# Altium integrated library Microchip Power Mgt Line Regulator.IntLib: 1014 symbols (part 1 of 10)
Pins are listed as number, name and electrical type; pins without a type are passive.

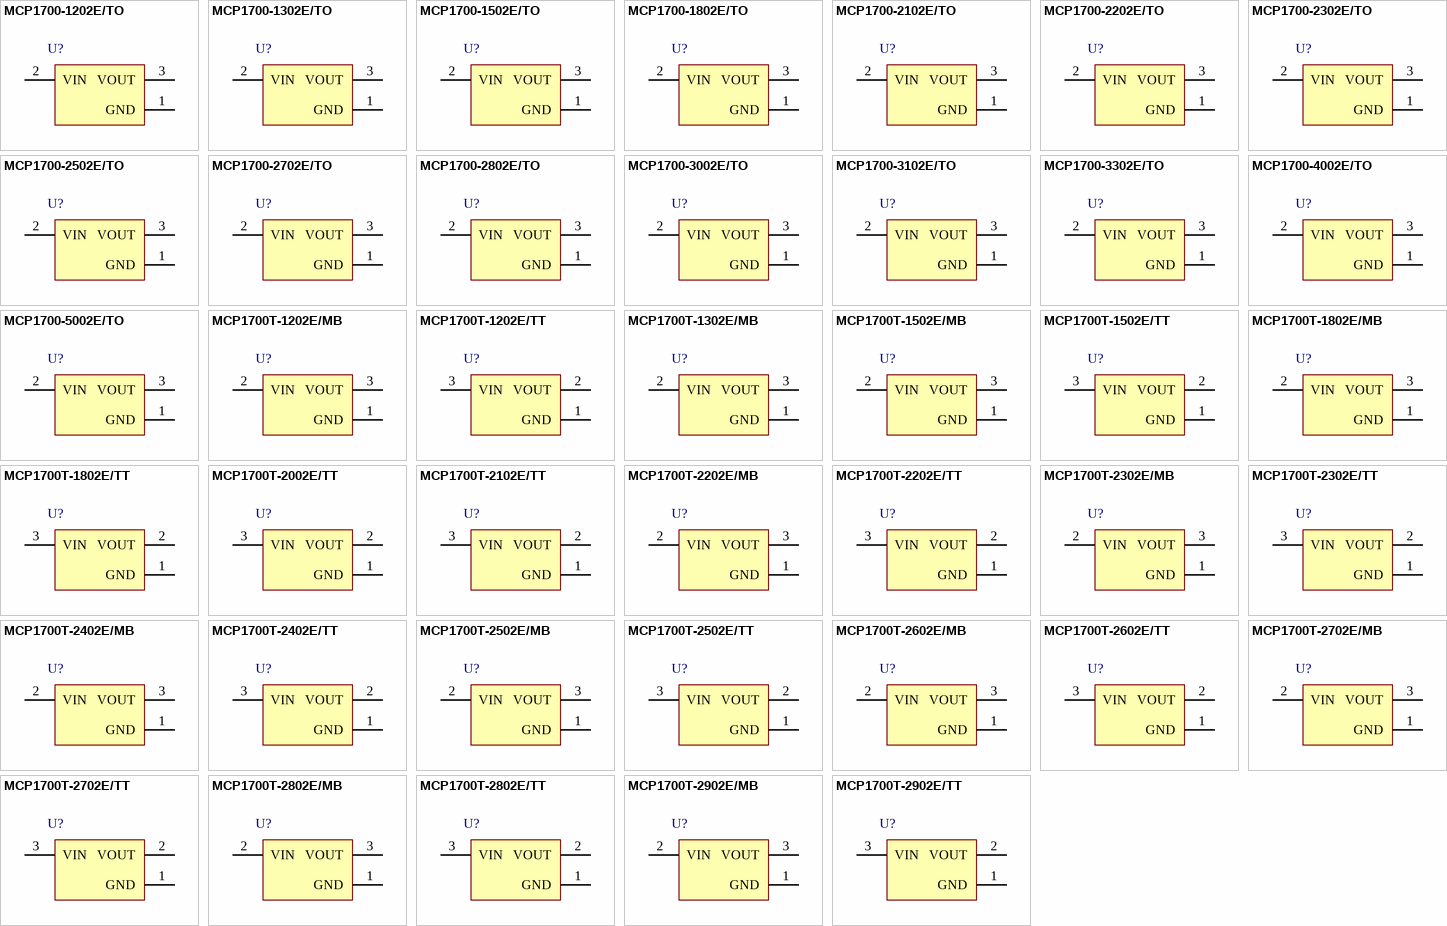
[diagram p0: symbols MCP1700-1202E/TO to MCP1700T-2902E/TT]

## MCP1700-1202E/TO
designator U?
Low Quiescent Current LDO, 3-Pin TO-92, Extended TemperatureBAG
footprint TO-92-TO3 (TO, Flat Index; 3 In-Line, Axial Leads; Body Dia. 4.8mm; Leads 0.56 x 0.53 mm (max))
pins: 1 GND (power), 2 VIN (power), 3 VOUT (power)

## MCP1700-1302E/TO
designator U?
Low Quiescent Current LDO, 3-Pin TO-92, Extended TemperatureBAG
footprint TO-92-TO3 (TO, Flat Index; 3 In-Line, Axial Leads; Body Dia. 4.8mm; Leads 0.56 x 0.53 mm (max))
pins: 1 GND (power), 2 VIN (power), 3 VOUT (power)

## MCP1700-1502E/TO
designator U?
Low Quiescent Current LDO, 3-Pin TO-92, Extended TemperatureBAG
footprint TO-92-TO3 (TO, Flat Index; 3 In-Line, Axial Leads; Body Dia. 4.8mm; Leads 0.56 x 0.53 mm (max))
pins: 1 GND (power), 2 VIN (power), 3 VOUT (power)

## MCP1700-1802E/TO
designator U?
Low Quiescent Current LDO, 3-Pin TO-92, Extended TemperatureBAG
footprint TO-92-TO3 (TO, Flat Index; 3 In-Line, Axial Leads; Body Dia. 4.8mm; Leads 0.56 x 0.53 mm (max))
pins: 1 GND (power), 2 VIN (power), 3 VOUT (power)

## MCP1700-2102E/TO
designator U?
Low Quiescent Current LDO, 3-Pin TO-92, Extended TemperatureBAG
footprint TO-92-TO3 (TO, Flat Index; 3 In-Line, Axial Leads; Body Dia. 4.8mm; Leads 0.56 x 0.53 mm (max))
pins: 1 GND (power), 2 VIN (power), 3 VOUT (power)

## MCP1700-2202E/TO
designator U?
Low Quiescent Current LDO, 3-Pin TO-92, Extended TemperatureBAG
footprint TO-92-TO3 (TO, Flat Index; 3 In-Line, Axial Leads; Body Dia. 4.8mm; Leads 0.56 x 0.53 mm (max))
pins: 1 GND (power), 2 VIN (power), 3 VOUT (power)

## MCP1700-2302E/TO
designator U?
Low Quiescent Current LDO, 3-Pin TO-92, Extended TemperatureBAG
footprint TO-92-TO3 (TO, Flat Index; 3 In-Line, Axial Leads; Body Dia. 4.8mm; Leads 0.56 x 0.53 mm (max))
pins: 1 GND (power), 2 VIN (power), 3 VOUT (power)

## MCP1700-2502E/TO
designator U?
Low Quiescent Current LDO, 3-Pin TO-92, Extended TemperatureBAG
footprint TO-92-TO3 (TO, Flat Index; 3 In-Line, Axial Leads; Body Dia. 4.8mm; Leads 0.56 x 0.53 mm (max))
pins: 1 GND (power), 2 VIN (power), 3 VOUT (power)

## MCP1700-2702E/TO
designator U?
Low Quiescent Current LDO, 3-Pin TO-92, Extended TemperatureBAG
footprint TO-92-TO3 (TO, Flat Index; 3 In-Line, Axial Leads; Body Dia. 4.8mm; Leads 0.56 x 0.53 mm (max))
pins: 1 GND (power), 2 VIN (power), 3 VOUT (power)

## MCP1700-2802E/TO
designator U?
Low Quiescent Current LDO, 3-Pin TO-92, Extended TemperatureBAG
footprint TO-92-TO3 (TO, Flat Index; 3 In-Line, Axial Leads; Body Dia. 4.8mm; Leads 0.56 x 0.53 mm (max))
pins: 1 GND (power), 2 VIN (power), 3 VOUT (power)

## MCP1700-3002E/TO
designator U?
Low Quiescent Current LDO, 3-Pin TO-92, Extended TemperatureBAG
footprint TO-92-TO3 (TO, Flat Index; 3 In-Line, Axial Leads; Body Dia. 4.8mm; Leads 0.56 x 0.53 mm (max))
pins: 1 GND (power), 2 VIN (power), 3 VOUT (power)

## MCP1700-3102E/TO
designator U?
Low Quiescent Current LDO, 3-Pin TO-92, Extended TemperatureBAG
footprint TO-92-TO3 (TO, Flat Index; 3 In-Line, Axial Leads; Body Dia. 4.8mm; Leads 0.56 x 0.53 mm (max))
pins: 1 GND (power), 2 VIN (power), 3 VOUT (power)

## MCP1700-3302E/TO
designator U?
Low Quiescent Current LDO, 3-Pin TO-92, Extended TemperatureBAG
footprint TO-92-TO3 (TO, Flat Index; 3 In-Line, Axial Leads; Body Dia. 4.8mm; Leads 0.56 x 0.53 mm (max))
pins: 1 GND (power), 2 VIN (power), 3 VOUT (power)

## MCP1700-4002E/TO
designator U?
Low Quiescent Current LDO, 3-Pin TO-92, Extended TemperatureBAG
footprint TO-92-TO3 (TO, Flat Index; 3 In-Line, Axial Leads; Body Dia. 4.8mm; Leads 0.56 x 0.53 mm (max))
pins: 1 GND (power), 2 VIN (power), 3 VOUT (power)

## MCP1700-5002E/TO
designator U?
Low Quiescent Current LDO, 3-Pin TO-92, Extended TemperatureBAG
footprint TO-92-TO3 (TO, Flat Index; 3 In-Line, Axial Leads; Body Dia. 4.8mm; Leads 0.56 x 0.53 mm (max))
pins: 1 GND (power), 2 VIN (power), 3 VOUT (power)

## MCP1700T-1202E/MB
designator U?
Low Quiescent Current LDO, 3-Pin SOT-89, Extended Temperature, Tape and Reel
footprint SOT-89-MB3_N (SOT89, 3-Leads, Body 4.5x2.4 mm, Pitch 1.5mm, Lead Span 4.1mm, IPC Medium Density)
footprint SOT-89-MB3_L (SOT89, 3-Leads, Body 4.5x2.4 mm, Pitch 1.5mm, Lead Span 4.1mm, IPC High Density)
footprint SOT-89-MB3_M (SOT89, 3-Leads, Body 4.5x2.4 mm, Pitch 1.5mm, Lead Span 4.1mm, IPC Low Density)
pins: 1 GND (power), 2 VIN (power), 3 VOUT (power)

## MCP1700T-1202E/TT
designator U?
Low Quiescent Current LDO, 3-Pin SOT-23, Extended Temperature, Tape and Reel
footprint SOT-23-TT3_N (SOT23, 3-Leads, Body 2.9x1.3mm, Pitch 0.95mm, Lead Span 2.4mm, IPC Medium Density)
footprint SOT-23-TT3_L (SOT23, 3-Leads, Body 2.9x1.3mm, Pitch 0.95mm, Lead Span 2.4mm, IPC High Density)
footprint SOT-23-TT3_M (SOT23, 3-Leads, Body 2.9x1.3mm, Pitch 0.95mm, Lead Span 2.4mm, IPC Low Density)
pins: 1 GND (power), 2 VOUT (power), 3 VIN (power)

## MCP1700T-1302E/MB
designator U?
Low Quiescent Current LDO, 3-Pin SOT-89, Extended Temperature, Tape and Reel
footprint SOT-89-MB3_N (SOT89, 3-Leads, Body 4.5x2.4 mm, Pitch 1.5mm, Lead Span 4.1mm, IPC Medium Density)
footprint SOT-89-MB3_L (SOT89, 3-Leads, Body 4.5x2.4 mm, Pitch 1.5mm, Lead Span 4.1mm, IPC High Density)
footprint SOT-89-MB3_M (SOT89, 3-Leads, Body 4.5x2.4 mm, Pitch 1.5mm, Lead Span 4.1mm, IPC Low Density)
pins: 1 GND (power), 2 VIN (power), 3 VOUT (power)

## MCP1700T-1502E/MB
designator U?
Low Quiescent Current LDO, 3-Pin SOT-89, Extended Temperature, Tape and Reel
footprint SOT-89-MB3_N (SOT89, 3-Leads, Body 4.5x2.4 mm, Pitch 1.5mm, Lead Span 4.1mm, IPC Medium Density)
footprint SOT-89-MB3_L (SOT89, 3-Leads, Body 4.5x2.4 mm, Pitch 1.5mm, Lead Span 4.1mm, IPC High Density)
footprint SOT-89-MB3_M (SOT89, 3-Leads, Body 4.5x2.4 mm, Pitch 1.5mm, Lead Span 4.1mm, IPC Low Density)
pins: 1 GND (power), 2 VIN (power), 3 VOUT (power)

## MCP1700T-1502E/TT
designator U?
Low Quiescent Current LDO, 3-Pin SOT-23, Extended Temperature, Tape and Reel
footprint SOT-23-TT3_N (SOT23, 3-Leads, Body 2.9x1.3mm, Pitch 0.95mm, Lead Span 2.4mm, IPC Medium Density)
footprint SOT-23-TT3_L (SOT23, 3-Leads, Body 2.9x1.3mm, Pitch 0.95mm, Lead Span 2.4mm, IPC High Density)
footprint SOT-23-TT3_M (SOT23, 3-Leads, Body 2.9x1.3mm, Pitch 0.95mm, Lead Span 2.4mm, IPC Low Density)
pins: 1 GND (power), 2 VOUT (power), 3 VIN (power)

## MCP1700T-1802E/MB
designator U?
Low Quiescent Current LDO, 3-Pin SOT-89, Extended Temperature, Tape and Reel
footprint SOT-89-MB3_N (SOT89, 3-Leads, Body 4.5x2.4 mm, Pitch 1.5mm, Lead Span 4.1mm, IPC Medium Density)
footprint SOT-89-MB3_L (SOT89, 3-Leads, Body 4.5x2.4 mm, Pitch 1.5mm, Lead Span 4.1mm, IPC High Density)
footprint SOT-89-MB3_M (SOT89, 3-Leads, Body 4.5x2.4 mm, Pitch 1.5mm, Lead Span 4.1mm, IPC Low Density)
pins: 1 GND (power), 2 VIN (power), 3 VOUT (power)

## MCP1700T-1802E/TT
designator U?
Low Quiescent Current LDO, 3-Pin SOT-23, Extended Temperature, Tape and Reel
footprint SOT-23-TT3_N (SOT23, 3-Leads, Body 2.9x1.3mm, Pitch 0.95mm, Lead Span 2.4mm, IPC Medium Density)
footprint SOT-23-TT3_L (SOT23, 3-Leads, Body 2.9x1.3mm, Pitch 0.95mm, Lead Span 2.4mm, IPC High Density)
footprint SOT-23-TT3_M (SOT23, 3-Leads, Body 2.9x1.3mm, Pitch 0.95mm, Lead Span 2.4mm, IPC Low Density)
pins: 1 GND (power), 2 VOUT (power), 3 VIN (power)

## MCP1700T-2002E/TT
designator U?
Low Quiescent Current LDO, 3-Pin SOT-23, Extended Temperature, Tape and Reel
footprint SOT-23-TT3_N (SOT23, 3-Leads, Body 2.9x1.3mm, Pitch 0.95mm, Lead Span 2.4mm, IPC Medium Density)
footprint SOT-23-TT3_L (SOT23, 3-Leads, Body 2.9x1.3mm, Pitch 0.95mm, Lead Span 2.4mm, IPC High Density)
footprint SOT-23-TT3_M (SOT23, 3-Leads, Body 2.9x1.3mm, Pitch 0.95mm, Lead Span 2.4mm, IPC Low Density)
pins: 1 GND (power), 2 VOUT (power), 3 VIN (power)

## MCP1700T-2102E/TT
designator U?
Low Quiescent Current LDO, 3-Pin SOT-23, Extended Temperature, Tape and Reel
footprint SOT-23-TT3_N (SOT23, 3-Leads, Body 2.9x1.3mm, Pitch 0.95mm, Lead Span 2.4mm, IPC Medium Density)
footprint SOT-23-TT3_L (SOT23, 3-Leads, Body 2.9x1.3mm, Pitch 0.95mm, Lead Span 2.4mm, IPC High Density)
footprint SOT-23-TT3_M (SOT23, 3-Leads, Body 2.9x1.3mm, Pitch 0.95mm, Lead Span 2.4mm, IPC Low Density)
pins: 1 GND (power), 2 VOUT (power), 3 VIN (power)

## MCP1700T-2202E/MB
designator U?
Low Quiescent Current LDO, 3-Pin SOT-89, Extended Temperature, Tape and Reel
footprint SOT-89-MB3_N (SOT89, 3-Leads, Body 4.5x2.4 mm, Pitch 1.5mm, Lead Span 4.1mm, IPC Medium Density)
footprint SOT-89-MB3_L (SOT89, 3-Leads, Body 4.5x2.4 mm, Pitch 1.5mm, Lead Span 4.1mm, IPC High Density)
footprint SOT-89-MB3_M (SOT89, 3-Leads, Body 4.5x2.4 mm, Pitch 1.5mm, Lead Span 4.1mm, IPC Low Density)
pins: 1 GND (power), 2 VIN (power), 3 VOUT (power)

## MCP1700T-2202E/TT
designator U?
Low Quiescent Current LDO, 3-Pin SOT-23, Extended Temperature, Tape and Reel
footprint SOT-23-TT3_N (SOT23, 3-Leads, Body 2.9x1.3mm, Pitch 0.95mm, Lead Span 2.4mm, IPC Medium Density)
footprint SOT-23-TT3_L (SOT23, 3-Leads, Body 2.9x1.3mm, Pitch 0.95mm, Lead Span 2.4mm, IPC High Density)
footprint SOT-23-TT3_M (SOT23, 3-Leads, Body 2.9x1.3mm, Pitch 0.95mm, Lead Span 2.4mm, IPC Low Density)
pins: 1 GND (power), 2 VOUT (power), 3 VIN (power)

## MCP1700T-2302E/MB
designator U?
Low Quiescent Current LDO, 3-Pin SOT-89, Extended Temperature, Tape and Reel
footprint SOT-89-MB3_N (SOT89, 3-Leads, Body 4.5x2.4 mm, Pitch 1.5mm, Lead Span 4.1mm, IPC Medium Density)
footprint SOT-89-MB3_L (SOT89, 3-Leads, Body 4.5x2.4 mm, Pitch 1.5mm, Lead Span 4.1mm, IPC High Density)
footprint SOT-89-MB3_M (SOT89, 3-Leads, Body 4.5x2.4 mm, Pitch 1.5mm, Lead Span 4.1mm, IPC Low Density)
pins: 1 GND (power), 2 VIN (power), 3 VOUT (power)

## MCP1700T-2302E/TT
designator U?
Low Quiescent Current LDO, 3-Pin SOT-23, Extended Temperature, Tape and Reel
footprint SOT-23-TT3_N (SOT23, 3-Leads, Body 2.9x1.3mm, Pitch 0.95mm, Lead Span 2.4mm, IPC Medium Density)
footprint SOT-23-TT3_L (SOT23, 3-Leads, Body 2.9x1.3mm, Pitch 0.95mm, Lead Span 2.4mm, IPC High Density)
footprint SOT-23-TT3_M (SOT23, 3-Leads, Body 2.9x1.3mm, Pitch 0.95mm, Lead Span 2.4mm, IPC Low Density)
pins: 1 GND (power), 2 VOUT (power), 3 VIN (power)

## MCP1700T-2402E/MB
designator U?
Low Quiescent Current LDO, 3-Pin SOT-89, Extended Temperature, Tape and Reel
footprint SOT-89-MB3_N (SOT89, 3-Leads, Body 4.5x2.4 mm, Pitch 1.5mm, Lead Span 4.1mm, IPC Medium Density)
footprint SOT-89-MB3_L (SOT89, 3-Leads, Body 4.5x2.4 mm, Pitch 1.5mm, Lead Span 4.1mm, IPC High Density)
footprint SOT-89-MB3_M (SOT89, 3-Leads, Body 4.5x2.4 mm, Pitch 1.5mm, Lead Span 4.1mm, IPC Low Density)
pins: 1 GND (power), 2 VIN (power), 3 VOUT (power)

## MCP1700T-2402E/TT
designator U?
Low Quiescent Current LDO, 3-Pin SOT-23, Extended Temperature, Tape and Reel
footprint SOT-23-TT3_N (SOT23, 3-Leads, Body 2.9x1.3mm, Pitch 0.95mm, Lead Span 2.4mm, IPC Medium Density)
footprint SOT-23-TT3_L (SOT23, 3-Leads, Body 2.9x1.3mm, Pitch 0.95mm, Lead Span 2.4mm, IPC High Density)
footprint SOT-23-TT3_M (SOT23, 3-Leads, Body 2.9x1.3mm, Pitch 0.95mm, Lead Span 2.4mm, IPC Low Density)
pins: 1 GND (power), 2 VOUT (power), 3 VIN (power)

## MCP1700T-2502E/MB
designator U?
Low Quiescent Current LDO, 3-Pin SOT-89, Extended Temperature, Tape and Reel
footprint SOT-89-MB3_N (SOT89, 3-Leads, Body 4.5x2.4 mm, Pitch 1.5mm, Lead Span 4.1mm, IPC Medium Density)
footprint SOT-89-MB3_L (SOT89, 3-Leads, Body 4.5x2.4 mm, Pitch 1.5mm, Lead Span 4.1mm, IPC High Density)
footprint SOT-89-MB3_M (SOT89, 3-Leads, Body 4.5x2.4 mm, Pitch 1.5mm, Lead Span 4.1mm, IPC Low Density)
pins: 1 GND (power), 2 VIN (power), 3 VOUT (power)

## MCP1700T-2502E/TT
designator U?
Low Quiescent Current LDO, 3-Pin SOT-23, Extended Temperature, Tape and Reel
footprint SOT-23-TT3_N (SOT23, 3-Leads, Body 2.9x1.3mm, Pitch 0.95mm, Lead Span 2.4mm, IPC Medium Density)
footprint SOT-23-TT3_L (SOT23, 3-Leads, Body 2.9x1.3mm, Pitch 0.95mm, Lead Span 2.4mm, IPC High Density)
footprint SOT-23-TT3_M (SOT23, 3-Leads, Body 2.9x1.3mm, Pitch 0.95mm, Lead Span 2.4mm, IPC Low Density)
pins: 1 GND (power), 2 VOUT (power), 3 VIN (power)

## MCP1700T-2602E/MB
designator U?
Low Quiescent Current LDO, 3-Pin SOT-89, Extended Temperature, Tape and Reel
footprint SOT-89-MB3_N (SOT89, 3-Leads, Body 4.5x2.4 mm, Pitch 1.5mm, Lead Span 4.1mm, IPC Medium Density)
footprint SOT-89-MB3_L (SOT89, 3-Leads, Body 4.5x2.4 mm, Pitch 1.5mm, Lead Span 4.1mm, IPC High Density)
footprint SOT-89-MB3_M (SOT89, 3-Leads, Body 4.5x2.4 mm, Pitch 1.5mm, Lead Span 4.1mm, IPC Low Density)
pins: 1 GND (power), 2 VIN (power), 3 VOUT (power)

## MCP1700T-2602E/TT
designator U?
Low Quiescent Current LDO, 3-Pin SOT-23, Extended Temperature, Tape and Reel
footprint SOT-23-TT3_N (SOT23, 3-Leads, Body 2.9x1.3mm, Pitch 0.95mm, Lead Span 2.4mm, IPC Medium Density)
footprint SOT-23-TT3_L (SOT23, 3-Leads, Body 2.9x1.3mm, Pitch 0.95mm, Lead Span 2.4mm, IPC High Density)
footprint SOT-23-TT3_M (SOT23, 3-Leads, Body 2.9x1.3mm, Pitch 0.95mm, Lead Span 2.4mm, IPC Low Density)
pins: 1 GND (power), 2 VOUT (power), 3 VIN (power)

## MCP1700T-2702E/MB
designator U?
Low Quiescent Current LDO, 3-Pin SOT-89, Extended Temperature, Tape and Reel
footprint SOT-89-MB3_N (SOT89, 3-Leads, Body 4.5x2.4 mm, Pitch 1.5mm, Lead Span 4.1mm, IPC Medium Density)
footprint SOT-89-MB3_L (SOT89, 3-Leads, Body 4.5x2.4 mm, Pitch 1.5mm, Lead Span 4.1mm, IPC High Density)
footprint SOT-89-MB3_M (SOT89, 3-Leads, Body 4.5x2.4 mm, Pitch 1.5mm, Lead Span 4.1mm, IPC Low Density)
pins: 1 GND (power), 2 VIN (power), 3 VOUT (power)

## MCP1700T-2702E/TT
designator U?
Low Quiescent Current LDO, 3-Pin SOT-23, Extended Temperature, Tape and Reel
footprint SOT-23-TT3_N (SOT23, 3-Leads, Body 2.9x1.3mm, Pitch 0.95mm, Lead Span 2.4mm, IPC Medium Density)
footprint SOT-23-TT3_L (SOT23, 3-Leads, Body 2.9x1.3mm, Pitch 0.95mm, Lead Span 2.4mm, IPC High Density)
footprint SOT-23-TT3_M (SOT23, 3-Leads, Body 2.9x1.3mm, Pitch 0.95mm, Lead Span 2.4mm, IPC Low Density)
pins: 1 GND (power), 2 VOUT (power), 3 VIN (power)

## MCP1700T-2802E/MB
designator U?
Low Quiescent Current LDO, 3-Pin SOT-89, Extended Temperature, Tape and Reel
footprint SOT-89-MB3_N (SOT89, 3-Leads, Body 4.5x2.4 mm, Pitch 1.5mm, Lead Span 4.1mm, IPC Medium Density)
footprint SOT-89-MB3_L (SOT89, 3-Leads, Body 4.5x2.4 mm, Pitch 1.5mm, Lead Span 4.1mm, IPC High Density)
footprint SOT-89-MB3_M (SOT89, 3-Leads, Body 4.5x2.4 mm, Pitch 1.5mm, Lead Span 4.1mm, IPC Low Density)
pins: 1 GND (power), 2 VIN (power), 3 VOUT (power)

## MCP1700T-2802E/TT
designator U?
Low Quiescent Current LDO, 3-Pin SOT-23, Extended Temperature, Tape and Reel
footprint SOT-23-TT3_N (SOT23, 3-Leads, Body 2.9x1.3mm, Pitch 0.95mm, Lead Span 2.4mm, IPC Medium Density)
footprint SOT-23-TT3_L (SOT23, 3-Leads, Body 2.9x1.3mm, Pitch 0.95mm, Lead Span 2.4mm, IPC High Density)
footprint SOT-23-TT3_M (SOT23, 3-Leads, Body 2.9x1.3mm, Pitch 0.95mm, Lead Span 2.4mm, IPC Low Density)
pins: 1 GND (power), 2 VOUT (power), 3 VIN (power)

## MCP1700T-2902E/MB
designator U?
Low Quiescent Current LDO, 3-Pin SOT-89, Extended Temperature, Tape and Reel
footprint SOT-89-MB3_N (SOT89, 3-Leads, Body 4.5x2.4 mm, Pitch 1.5mm, Lead Span 4.1mm, IPC Medium Density)
footprint SOT-89-MB3_L (SOT89, 3-Leads, Body 4.5x2.4 mm, Pitch 1.5mm, Lead Span 4.1mm, IPC High Density)
footprint SOT-89-MB3_M (SOT89, 3-Leads, Body 4.5x2.4 mm, Pitch 1.5mm, Lead Span 4.1mm, IPC Low Density)
pins: 1 GND (power), 2 VIN (power), 3 VOUT (power)

## MCP1700T-2902E/TT
designator U?
Low Quiescent Current LDO, 3-Pin SOT-23, Extended Temperature, Tape and Reel
footprint SOT-23-TT3_N (SOT23, 3-Leads, Body 2.9x1.3mm, Pitch 0.95mm, Lead Span 2.4mm, IPC Medium Density)
footprint SOT-23-TT3_L (SOT23, 3-Leads, Body 2.9x1.3mm, Pitch 0.95mm, Lead Span 2.4mm, IPC High Density)
footprint SOT-23-TT3_M (SOT23, 3-Leads, Body 2.9x1.3mm, Pitch 0.95mm, Lead Span 2.4mm, IPC Low Density)
pins: 1 GND (power), 2 VOUT (power), 3 VIN (power)

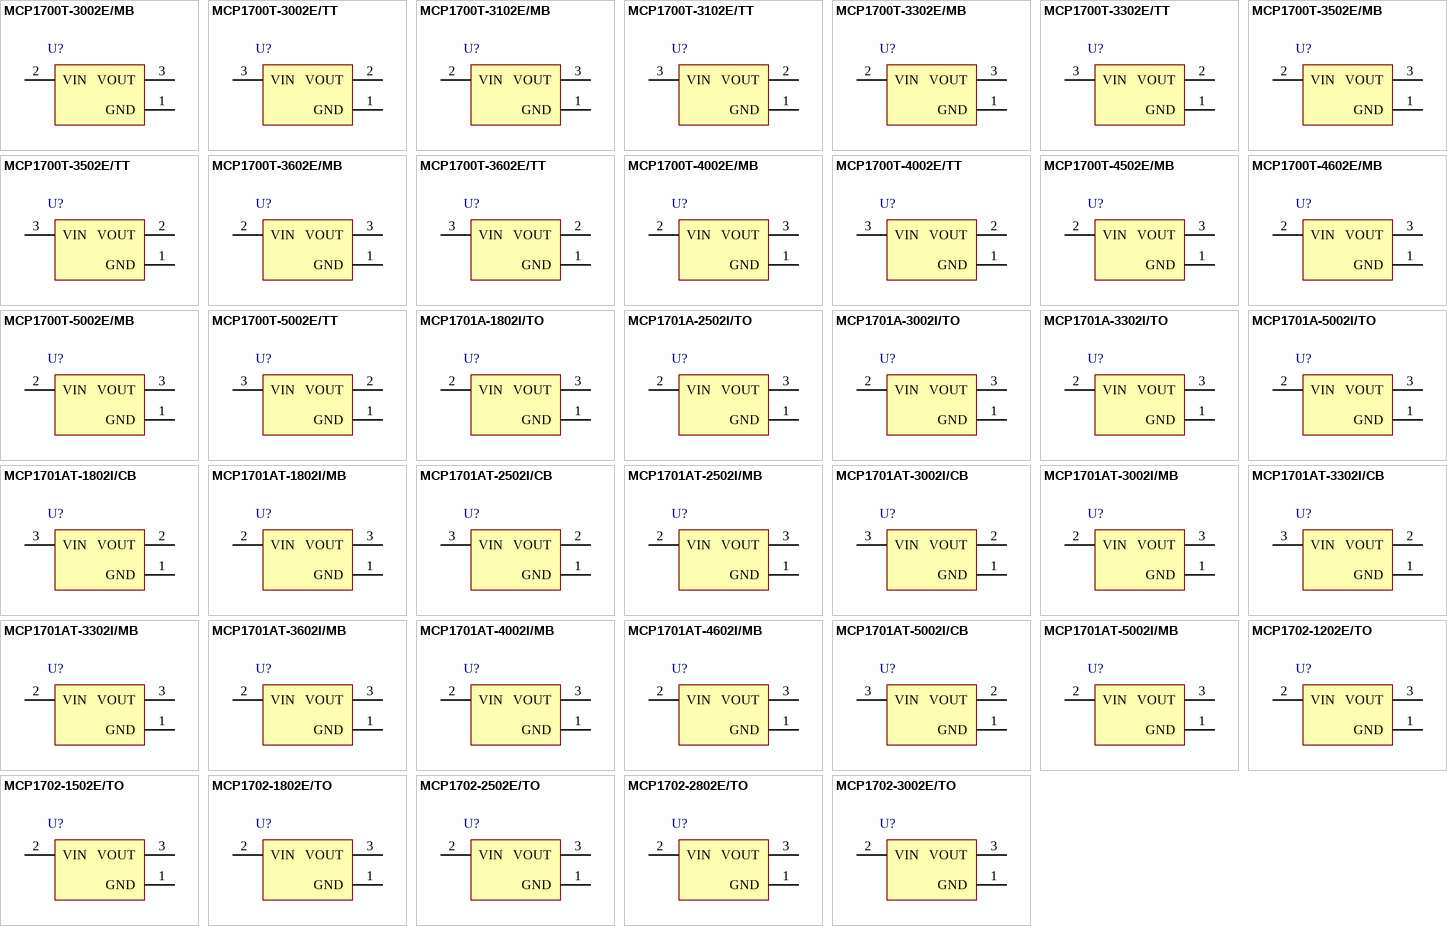
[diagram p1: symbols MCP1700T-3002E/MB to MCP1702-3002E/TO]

## MCP1700T-3002E/MB
designator U?
Low Quiescent Current LDO, 3-Pin SOT-89, Extended Temperature, Tape and Reel
footprint SOT-89-MB3_N (SOT89, 3-Leads, Body 4.5x2.4 mm, Pitch 1.5mm, Lead Span 4.1mm, IPC Medium Density)
footprint SOT-89-MB3_L (SOT89, 3-Leads, Body 4.5x2.4 mm, Pitch 1.5mm, Lead Span 4.1mm, IPC High Density)
footprint SOT-89-MB3_M (SOT89, 3-Leads, Body 4.5x2.4 mm, Pitch 1.5mm, Lead Span 4.1mm, IPC Low Density)
pins: 1 GND (power), 2 VIN (power), 3 VOUT (power)

## MCP1700T-3002E/TT
designator U?
Low Quiescent Current LDO, 3-Pin SOT-23, Extended Temperature, Tape and Reel
footprint SOT-23-TT3_N (SOT23, 3-Leads, Body 2.9x1.3mm, Pitch 0.95mm, Lead Span 2.4mm, IPC Medium Density)
footprint SOT-23-TT3_L (SOT23, 3-Leads, Body 2.9x1.3mm, Pitch 0.95mm, Lead Span 2.4mm, IPC High Density)
footprint SOT-23-TT3_M (SOT23, 3-Leads, Body 2.9x1.3mm, Pitch 0.95mm, Lead Span 2.4mm, IPC Low Density)
pins: 1 GND (power), 2 VOUT (power), 3 VIN (power)

## MCP1700T-3102E/MB
designator U?
Low Quiescent Current LDO, 3-Pin SOT-89, Extended Temperature, Tape and Reel
footprint SOT-89-MB3_N (SOT89, 3-Leads, Body 4.5x2.4 mm, Pitch 1.5mm, Lead Span 4.1mm, IPC Medium Density)
footprint SOT-89-MB3_L (SOT89, 3-Leads, Body 4.5x2.4 mm, Pitch 1.5mm, Lead Span 4.1mm, IPC High Density)
footprint SOT-89-MB3_M (SOT89, 3-Leads, Body 4.5x2.4 mm, Pitch 1.5mm, Lead Span 4.1mm, IPC Low Density)
pins: 1 GND (power), 2 VIN (power), 3 VOUT (power)

## MCP1700T-3102E/TT
designator U?
Low Quiescent Current LDO, 3-Pin SOT-23, Extended Temperature, Tape and Reel
footprint SOT-23-TT3_N (SOT23, 3-Leads, Body 2.9x1.3mm, Pitch 0.95mm, Lead Span 2.4mm, IPC Medium Density)
footprint SOT-23-TT3_L (SOT23, 3-Leads, Body 2.9x1.3mm, Pitch 0.95mm, Lead Span 2.4mm, IPC High Density)
footprint SOT-23-TT3_M (SOT23, 3-Leads, Body 2.9x1.3mm, Pitch 0.95mm, Lead Span 2.4mm, IPC Low Density)
pins: 1 GND (power), 2 VOUT (power), 3 VIN (power)

## MCP1700T-3302E/MB
designator U?
Low Quiescent Current LDO, 3-Pin SOT-89, Extended Temperature, Tape and Reel
footprint SOT-89-MB3_N (SOT89, 3-Leads, Body 4.5x2.4 mm, Pitch 1.5mm, Lead Span 4.1mm, IPC Medium Density)
footprint SOT-89-MB3_L (SOT89, 3-Leads, Body 4.5x2.4 mm, Pitch 1.5mm, Lead Span 4.1mm, IPC High Density)
footprint SOT-89-MB3_M (SOT89, 3-Leads, Body 4.5x2.4 mm, Pitch 1.5mm, Lead Span 4.1mm, IPC Low Density)
pins: 1 GND (power), 2 VIN (power), 3 VOUT (power)

## MCP1700T-3302E/TT
designator U?
Low Quiescent Current LDO, 3-Pin SOT-23, Extended Temperature, Tape and Reel
footprint SOT-23-TT3_N (SOT23, 3-Leads, Body 2.9x1.3mm, Pitch 0.95mm, Lead Span 2.4mm, IPC Medium Density)
footprint SOT-23-TT3_L (SOT23, 3-Leads, Body 2.9x1.3mm, Pitch 0.95mm, Lead Span 2.4mm, IPC High Density)
footprint SOT-23-TT3_M (SOT23, 3-Leads, Body 2.9x1.3mm, Pitch 0.95mm, Lead Span 2.4mm, IPC Low Density)
pins: 1 GND (power), 2 VOUT (power), 3 VIN (power)

## MCP1700T-3502E/MB
designator U?
Low Quiescent Current LDO, 3-Pin SOT-89, Extended Temperature, Tape and Reel
footprint SOT-89-MB3_N (SOT89, 3-Leads, Body 4.5x2.4 mm, Pitch 1.5mm, Lead Span 4.1mm, IPC Medium Density)
footprint SOT-89-MB3_L (SOT89, 3-Leads, Body 4.5x2.4 mm, Pitch 1.5mm, Lead Span 4.1mm, IPC High Density)
footprint SOT-89-MB3_M (SOT89, 3-Leads, Body 4.5x2.4 mm, Pitch 1.5mm, Lead Span 4.1mm, IPC Low Density)
pins: 1 GND (power), 2 VIN (power), 3 VOUT (power)

## MCP1700T-3502E/TT
designator U?
Low Quiescent Current LDO, 3-Pin SOT-23, Extended Temperature, Tape and Reel
footprint SOT-23-TT3_N (SOT23, 3-Leads, Body 2.9x1.3mm, Pitch 0.95mm, Lead Span 2.4mm, IPC Medium Density)
footprint SOT-23-TT3_L (SOT23, 3-Leads, Body 2.9x1.3mm, Pitch 0.95mm, Lead Span 2.4mm, IPC High Density)
footprint SOT-23-TT3_M (SOT23, 3-Leads, Body 2.9x1.3mm, Pitch 0.95mm, Lead Span 2.4mm, IPC Low Density)
pins: 1 GND (power), 2 VOUT (power), 3 VIN (power)

## MCP1700T-3602E/MB
designator U?
Low Quiescent Current LDO, 3-Pin SOT-89, Extended Temperature, Tape and Reel
footprint SOT-89-MB3_N (SOT89, 3-Leads, Body 4.5x2.4 mm, Pitch 1.5mm, Lead Span 4.1mm, IPC Medium Density)
footprint SOT-89-MB3_L (SOT89, 3-Leads, Body 4.5x2.4 mm, Pitch 1.5mm, Lead Span 4.1mm, IPC High Density)
footprint SOT-89-MB3_M (SOT89, 3-Leads, Body 4.5x2.4 mm, Pitch 1.5mm, Lead Span 4.1mm, IPC Low Density)
pins: 1 GND (power), 2 VIN (power), 3 VOUT (power)

## MCP1700T-3602E/TT
designator U?
Low Quiescent Current LDO, 3-Pin SOT-23, Extended Temperature, Tape and Reel
footprint SOT-23-TT3_N (SOT23, 3-Leads, Body 2.9x1.3mm, Pitch 0.95mm, Lead Span 2.4mm, IPC Medium Density)
footprint SOT-23-TT3_L (SOT23, 3-Leads, Body 2.9x1.3mm, Pitch 0.95mm, Lead Span 2.4mm, IPC High Density)
footprint SOT-23-TT3_M (SOT23, 3-Leads, Body 2.9x1.3mm, Pitch 0.95mm, Lead Span 2.4mm, IPC Low Density)
pins: 1 GND (power), 2 VOUT (power), 3 VIN (power)

## MCP1700T-4002E/MB
designator U?
Low Quiescent Current LDO, 3-Pin SOT-89, Extended Temperature, Tape and Reel
footprint SOT-89-MB3_N (SOT89, 3-Leads, Body 4.5x2.4 mm, Pitch 1.5mm, Lead Span 4.1mm, IPC Medium Density)
footprint SOT-89-MB3_L (SOT89, 3-Leads, Body 4.5x2.4 mm, Pitch 1.5mm, Lead Span 4.1mm, IPC High Density)
footprint SOT-89-MB3_M (SOT89, 3-Leads, Body 4.5x2.4 mm, Pitch 1.5mm, Lead Span 4.1mm, IPC Low Density)
pins: 1 GND (power), 2 VIN (power), 3 VOUT (power)

## MCP1700T-4002E/TT
designator U?
Low Quiescent Current LDO, 3-Pin SOT-23, Extended Temperature, Tape and Reel
footprint SOT-23-TT3_N (SOT23, 3-Leads, Body 2.9x1.3mm, Pitch 0.95mm, Lead Span 2.4mm, IPC Medium Density)
footprint SOT-23-TT3_L (SOT23, 3-Leads, Body 2.9x1.3mm, Pitch 0.95mm, Lead Span 2.4mm, IPC High Density)
footprint SOT-23-TT3_M (SOT23, 3-Leads, Body 2.9x1.3mm, Pitch 0.95mm, Lead Span 2.4mm, IPC Low Density)
pins: 1 GND (power), 2 VOUT (power), 3 VIN (power)

## MCP1700T-4502E/MB
designator U?
Low Quiescent Current LDO, 3-Pin SOT-89, Extended Temperature, Tape and Reel
footprint SOT-89-MB3_N (SOT89, 3-Leads, Body 4.5x2.4 mm, Pitch 1.5mm, Lead Span 4.1mm, IPC Medium Density)
footprint SOT-89-MB3_L (SOT89, 3-Leads, Body 4.5x2.4 mm, Pitch 1.5mm, Lead Span 4.1mm, IPC High Density)
footprint SOT-89-MB3_M (SOT89, 3-Leads, Body 4.5x2.4 mm, Pitch 1.5mm, Lead Span 4.1mm, IPC Low Density)
pins: 1 GND (power), 2 VIN (power), 3 VOUT (power)

## MCP1700T-4602E/MB
designator U?
Low Quiescent Current LDO, 3-Pin SOT-89, Extended Temperature, Tape and Reel
footprint SOT-89-MB3_N (SOT89, 3-Leads, Body 4.5x2.4 mm, Pitch 1.5mm, Lead Span 4.1mm, IPC Medium Density)
footprint SOT-89-MB3_L (SOT89, 3-Leads, Body 4.5x2.4 mm, Pitch 1.5mm, Lead Span 4.1mm, IPC High Density)
footprint SOT-89-MB3_M (SOT89, 3-Leads, Body 4.5x2.4 mm, Pitch 1.5mm, Lead Span 4.1mm, IPC Low Density)
pins: 1 GND (power), 2 VIN (power), 3 VOUT (power)

## MCP1700T-5002E/MB
designator U?
Low Quiescent Current LDO, 3-Pin SOT-89, Extended Temperature, Tape and Reel
footprint SOT-89-MB3_N (SOT89, 3-Leads, Body 4.5x2.4 mm, Pitch 1.5mm, Lead Span 4.1mm, IPC Medium Density)
footprint SOT-89-MB3_L (SOT89, 3-Leads, Body 4.5x2.4 mm, Pitch 1.5mm, Lead Span 4.1mm, IPC High Density)
footprint SOT-89-MB3_M (SOT89, 3-Leads, Body 4.5x2.4 mm, Pitch 1.5mm, Lead Span 4.1mm, IPC Low Density)
pins: 1 GND (power), 2 VIN (power), 3 VOUT (power)

## MCP1700T-5002E/TT
designator U?
Low Quiescent Current LDO, 3-Pin SOT-23, Extended Temperature, Tape and Reel
footprint SOT-23-TT3_N (SOT23, 3-Leads, Body 2.9x1.3mm, Pitch 0.95mm, Lead Span 2.4mm, IPC Medium Density)
footprint SOT-23-TT3_L (SOT23, 3-Leads, Body 2.9x1.3mm, Pitch 0.95mm, Lead Span 2.4mm, IPC High Density)
footprint SOT-23-TT3_M (SOT23, 3-Leads, Body 2.9x1.3mm, Pitch 0.95mm, Lead Span 2.4mm, IPC Low Density)
pins: 1 GND (power), 2 VOUT (power), 3 VIN (power)

## MCP1701A-1802I/TO
designator U?
2 µA Low-Dropout Positive Voltage Regulator, 3-Pin TO-92, Industrial TemperatureBAG
footprint TO-92-TO3 (TO, Flat Index; 3 In-Line, Axial Leads; Body Dia. 4.8mm; Leads 0.56 x 0.53 mm (max))
pins: 1 GND (power), 2 VIN (power), 3 VOUT (power)

## MCP1701A-2502I/TO
designator U?
2 µA Low-Dropout Positive Voltage Regulator, 3-Pin TO-92, Industrial TemperatureBAG
footprint TO-92-TO3 (TO, Flat Index; 3 In-Line, Axial Leads; Body Dia. 4.8mm; Leads 0.56 x 0.53 mm (max))
pins: 1 GND (power), 2 VIN (power), 3 VOUT (power)

## MCP1701A-3002I/TO
designator U?
2 µA Low-Dropout Positive Voltage Regulator, 3-Pin TO-92, Industrial TemperatureBAG
footprint TO-92-TO3 (TO, Flat Index; 3 In-Line, Axial Leads; Body Dia. 4.8mm; Leads 0.56 x 0.53 mm (max))
pins: 1 GND (power), 2 VIN (power), 3 VOUT (power)

## MCP1701A-3302I/TO
designator U?
2 µA Low-Dropout Positive Voltage Regulator, 3-Pin TO-92, Industrial TemperatureBAG
footprint TO-92-TO3 (TO, Flat Index; 3 In-Line, Axial Leads; Body Dia. 4.8mm; Leads 0.56 x 0.53 mm (max))
pins: 1 GND (power), 2 VIN (power), 3 VOUT (power)

## MCP1701A-5002I/TO
designator U?
2 µA Low-Dropout Positive Voltage Regulator, 3-Pin TO-92, Industrial TemperatureBAG
footprint TO-92-TO3 (TO, Flat Index; 3 In-Line, Axial Leads; Body Dia. 4.8mm; Leads 0.56 x 0.53 mm (max))
pins: 1 GND (power), 2 VIN (power), 3 VOUT (power)

## MCP1701AT-1802I/CB
designator U?
2 µA Low-Dropout Positive Voltage Regulator, 3-Pin SOT-23A, Industrial Temperature, Tape and Reel
footprint SOT-23A-CB3_N (SOT346, 3-Leads, Body 2.9x1.5mm, Pitch 0.95mm, Lead Span 2.6mm, IPC Medium Density)
footprint SOT-23A-CB3_L (SOT346, 3-Leads, Body 2.9x1.5mm, Pitch 0.95mm, Lead Span 2.6mm, IPC High Density)
footprint SOT-23A-CB3_M (SOT346, 3-Leads, Body 2.9x1.5mm, Pitch 0.95mm, Lead Span 2.6mm, IPC Low Density)
pins: 1 GND (power), 2 VOUT (power), 3 VIN (power)

## MCP1701AT-1802I/MB
designator U?
2 µA Low-Dropout Positive Voltage Regulator, 3-Pin SOT-89, Industrial Temperature, Tape and Reel
footprint SOT-89-MB3_N (SOT89, 3-Leads, Body 4.5x2.4 mm, Pitch 1.5mm, Lead Span 4.1mm, IPC Medium Density)
footprint SOT-89-MB3_L (SOT89, 3-Leads, Body 4.5x2.4 mm, Pitch 1.5mm, Lead Span 4.1mm, IPC High Density)
footprint SOT-89-MB3_M (SOT89, 3-Leads, Body 4.5x2.4 mm, Pitch 1.5mm, Lead Span 4.1mm, IPC Low Density)
pins: 1 GND (power), 2 VIN (power), 3 VOUT (power)

## MCP1701AT-2502I/CB
designator U?
2 µA Low-Dropout Positive Voltage Regulator, 3-Pin SOT-23A, Industrial Temperature, Tape and Reel
footprint SOT-23A-CB3_N (SOT346, 3-Leads, Body 2.9x1.5mm, Pitch 0.95mm, Lead Span 2.6mm, IPC Medium Density)
footprint SOT-23A-CB3_L (SOT346, 3-Leads, Body 2.9x1.5mm, Pitch 0.95mm, Lead Span 2.6mm, IPC High Density)
footprint SOT-23A-CB3_M (SOT346, 3-Leads, Body 2.9x1.5mm, Pitch 0.95mm, Lead Span 2.6mm, IPC Low Density)
pins: 1 GND (power), 2 VOUT (power), 3 VIN (power)

## MCP1701AT-2502I/MB
designator U?
2 µA Low-Dropout Positive Voltage Regulator, 3-Pin SOT-89, Industrial Temperature, Tape and Reel
footprint SOT-89-MB3_N (SOT89, 3-Leads, Body 4.5x2.4 mm, Pitch 1.5mm, Lead Span 4.1mm, IPC Medium Density)
footprint SOT-89-MB3_L (SOT89, 3-Leads, Body 4.5x2.4 mm, Pitch 1.5mm, Lead Span 4.1mm, IPC High Density)
footprint SOT-89-MB3_M (SOT89, 3-Leads, Body 4.5x2.4 mm, Pitch 1.5mm, Lead Span 4.1mm, IPC Low Density)
pins: 1 GND (power), 2 VIN (power), 3 VOUT (power)

## MCP1701AT-3002I/CB
designator U?
2 µA Low-Dropout Positive Voltage Regulator, 3-Pin SOT-23A, Industrial Temperature, Tape and Reel
footprint SOT-23A-CB3_N (SOT346, 3-Leads, Body 2.9x1.5mm, Pitch 0.95mm, Lead Span 2.6mm, IPC Medium Density)
footprint SOT-23A-CB3_L (SOT346, 3-Leads, Body 2.9x1.5mm, Pitch 0.95mm, Lead Span 2.6mm, IPC High Density)
footprint SOT-23A-CB3_M (SOT346, 3-Leads, Body 2.9x1.5mm, Pitch 0.95mm, Lead Span 2.6mm, IPC Low Density)
pins: 1 GND (power), 2 VOUT (power), 3 VIN (power)

## MCP1701AT-3002I/MB
designator U?
2 µA Low-Dropout Positive Voltage Regulator, 3-Pin SOT-89, Industrial Temperature, Tape and Reel
footprint SOT-89-MB3_N (SOT89, 3-Leads, Body 4.5x2.4 mm, Pitch 1.5mm, Lead Span 4.1mm, IPC Medium Density)
footprint SOT-89-MB3_L (SOT89, 3-Leads, Body 4.5x2.4 mm, Pitch 1.5mm, Lead Span 4.1mm, IPC High Density)
footprint SOT-89-MB3_M (SOT89, 3-Leads, Body 4.5x2.4 mm, Pitch 1.5mm, Lead Span 4.1mm, IPC Low Density)
pins: 1 GND (power), 2 VIN (power), 3 VOUT (power)

## MCP1701AT-3302I/CB
designator U?
2 µA Low-Dropout Positive Voltage Regulator, 3-Pin SOT-23A, Industrial Temperature, Tape and Reel
footprint SOT-23A-CB3_N (SOT346, 3-Leads, Body 2.9x1.5mm, Pitch 0.95mm, Lead Span 2.6mm, IPC Medium Density)
footprint SOT-23A-CB3_L (SOT346, 3-Leads, Body 2.9x1.5mm, Pitch 0.95mm, Lead Span 2.6mm, IPC High Density)
footprint SOT-23A-CB3_M (SOT346, 3-Leads, Body 2.9x1.5mm, Pitch 0.95mm, Lead Span 2.6mm, IPC Low Density)
pins: 1 GND (power), 2 VOUT (power), 3 VIN (power)

## MCP1701AT-3302I/MB
designator U?
2 µA Low-Dropout Positive Voltage Regulator, 3-Pin SOT-89, Industrial Temperature, Tape and Reel
footprint SOT-89-MB3_N (SOT89, 3-Leads, Body 4.5x2.4 mm, Pitch 1.5mm, Lead Span 4.1mm, IPC Medium Density)
footprint SOT-89-MB3_L (SOT89, 3-Leads, Body 4.5x2.4 mm, Pitch 1.5mm, Lead Span 4.1mm, IPC High Density)
footprint SOT-89-MB3_M (SOT89, 3-Leads, Body 4.5x2.4 mm, Pitch 1.5mm, Lead Span 4.1mm, IPC Low Density)
pins: 1 GND (power), 2 VIN (power), 3 VOUT (power)

## MCP1701AT-3602I/MB
designator U?
2 µA Low-Dropout Positive Voltage Regulator, 3-Pin SOT-89, Industrial Temperature, Tape and Reel
footprint SOT-89-MB3_N (SOT89, 3-Leads, Body 4.5x2.4 mm, Pitch 1.5mm, Lead Span 4.1mm, IPC Medium Density)
footprint SOT-89-MB3_L (SOT89, 3-Leads, Body 4.5x2.4 mm, Pitch 1.5mm, Lead Span 4.1mm, IPC High Density)
footprint SOT-89-MB3_M (SOT89, 3-Leads, Body 4.5x2.4 mm, Pitch 1.5mm, Lead Span 4.1mm, IPC Low Density)
pins: 1 GND (power), 2 VIN (power), 3 VOUT (power)

## MCP1701AT-4002I/MB
designator U?
2 µA Low-Dropout Positive Voltage Regulator, 3-Pin SOT-89, Industrial Temperature, Tape and Reel
footprint SOT-89-MB3_N (SOT89, 3-Leads, Body 4.5x2.4 mm, Pitch 1.5mm, Lead Span 4.1mm, IPC Medium Density)
footprint SOT-89-MB3_L (SOT89, 3-Leads, Body 4.5x2.4 mm, Pitch 1.5mm, Lead Span 4.1mm, IPC High Density)
footprint SOT-89-MB3_M (SOT89, 3-Leads, Body 4.5x2.4 mm, Pitch 1.5mm, Lead Span 4.1mm, IPC Low Density)
pins: 1 GND (power), 2 VIN (power), 3 VOUT (power)

## MCP1701AT-4602I/MB
designator U?
2 µA Low-Dropout Positive Voltage Regulator, 3-Pin SOT-89, Industrial Temperature, Tape and Reel
footprint SOT-89-MB3_N (SOT89, 3-Leads, Body 4.5x2.4 mm, Pitch 1.5mm, Lead Span 4.1mm, IPC Medium Density)
footprint SOT-89-MB3_L (SOT89, 3-Leads, Body 4.5x2.4 mm, Pitch 1.5mm, Lead Span 4.1mm, IPC High Density)
footprint SOT-89-MB3_M (SOT89, 3-Leads, Body 4.5x2.4 mm, Pitch 1.5mm, Lead Span 4.1mm, IPC Low Density)
pins: 1 GND (power), 2 VIN (power), 3 VOUT (power)

## MCP1701AT-5002I/CB
designator U?
2 µA Low-Dropout Positive Voltage Regulator, 3-Pin SOT-23A, Industrial Temperature, Tape and Reel
footprint SOT-23A-CB3_N (SOT346, 3-Leads, Body 2.9x1.5mm, Pitch 0.95mm, Lead Span 2.6mm, IPC Medium Density)
footprint SOT-23A-CB3_L (SOT346, 3-Leads, Body 2.9x1.5mm, Pitch 0.95mm, Lead Span 2.6mm, IPC High Density)
footprint SOT-23A-CB3_M (SOT346, 3-Leads, Body 2.9x1.5mm, Pitch 0.95mm, Lead Span 2.6mm, IPC Low Density)
pins: 1 GND (power), 2 VOUT (power), 3 VIN (power)

## MCP1701AT-5002I/MB
designator U?
2 µA Low-Dropout Positive Voltage Regulator, 3-Pin SOT-89, Industrial Temperature, Tape and Reel
footprint SOT-89-MB3_N (SOT89, 3-Leads, Body 4.5x2.4 mm, Pitch 1.5mm, Lead Span 4.1mm, IPC Medium Density)
footprint SOT-89-MB3_L (SOT89, 3-Leads, Body 4.5x2.4 mm, Pitch 1.5mm, Lead Span 4.1mm, IPC High Density)
footprint SOT-89-MB3_M (SOT89, 3-Leads, Body 4.5x2.4 mm, Pitch 1.5mm, Lead Span 4.1mm, IPC Low Density)
pins: 1 GND (power), 2 VIN (power), 3 VOUT (power)

## MCP1702-1202E/TO
designator U?
250 mA Low Quiescent Current LDO Regulator, 3-Pin TO-92, Extended TemperatureBAG
footprint TO-92-TO3 (TO, Flat Index; 3 In-Line, Axial Leads; Body Dia. 4.8mm; Leads 0.56 x 0.53 mm (max))
pins: 1 GND (power), 2 VIN (power), 3 VOUT (power)

## MCP1702-1502E/TO
designator U?
250 mA Low Quiescent Current LDO Regulator, 3-Pin TO-92, Extended TemperatureBAG
footprint TO-92-TO3 (TO, Flat Index; 3 In-Line, Axial Leads; Body Dia. 4.8mm; Leads 0.56 x 0.53 mm (max))
pins: 1 GND (power), 2 VIN (power), 3 VOUT (power)

## MCP1702-1802E/TO
designator U?
250 mA Low Quiescent Current LDO Regulator, 3-Pin TO-92, Extended TemperatureBAG
footprint TO-92-TO3 (TO, Flat Index; 3 In-Line, Axial Leads; Body Dia. 4.8mm; Leads 0.56 x 0.53 mm (max))
pins: 1 GND (power), 2 VIN (power), 3 VOUT (power)

## MCP1702-2502E/TO
designator U?
250 mA Low Quiescent Current LDO Regulator, 3-Pin TO-92, Extended TemperatureBAG
footprint TO-92-TO3 (TO, Flat Index; 3 In-Line, Axial Leads; Body Dia. 4.8mm; Leads 0.56 x 0.53 mm (max))
pins: 1 GND (power), 2 VIN (power), 3 VOUT (power)

## MCP1702-2802E/TO
designator U?
250 mA Low Quiescent Current LDO Regulator, 3-Pin TO-92, Extended TemperatureBAG
footprint TO-92-TO3 (TO, Flat Index; 3 In-Line, Axial Leads; Body Dia. 4.8mm; Leads 0.56 x 0.53 mm (max))
pins: 1 GND (power), 2 VIN (power), 3 VOUT (power)

## MCP1702-3002E/TO
designator U?
250 mA Low Quiescent Current LDO Regulator, 3-Pin TO-92, Extended TemperatureBAG
footprint TO-92-TO3 (TO, Flat Index; 3 In-Line, Axial Leads; Body Dia. 4.8mm; Leads 0.56 x 0.53 mm (max))
pins: 1 GND (power), 2 VIN (power), 3 VOUT (power)

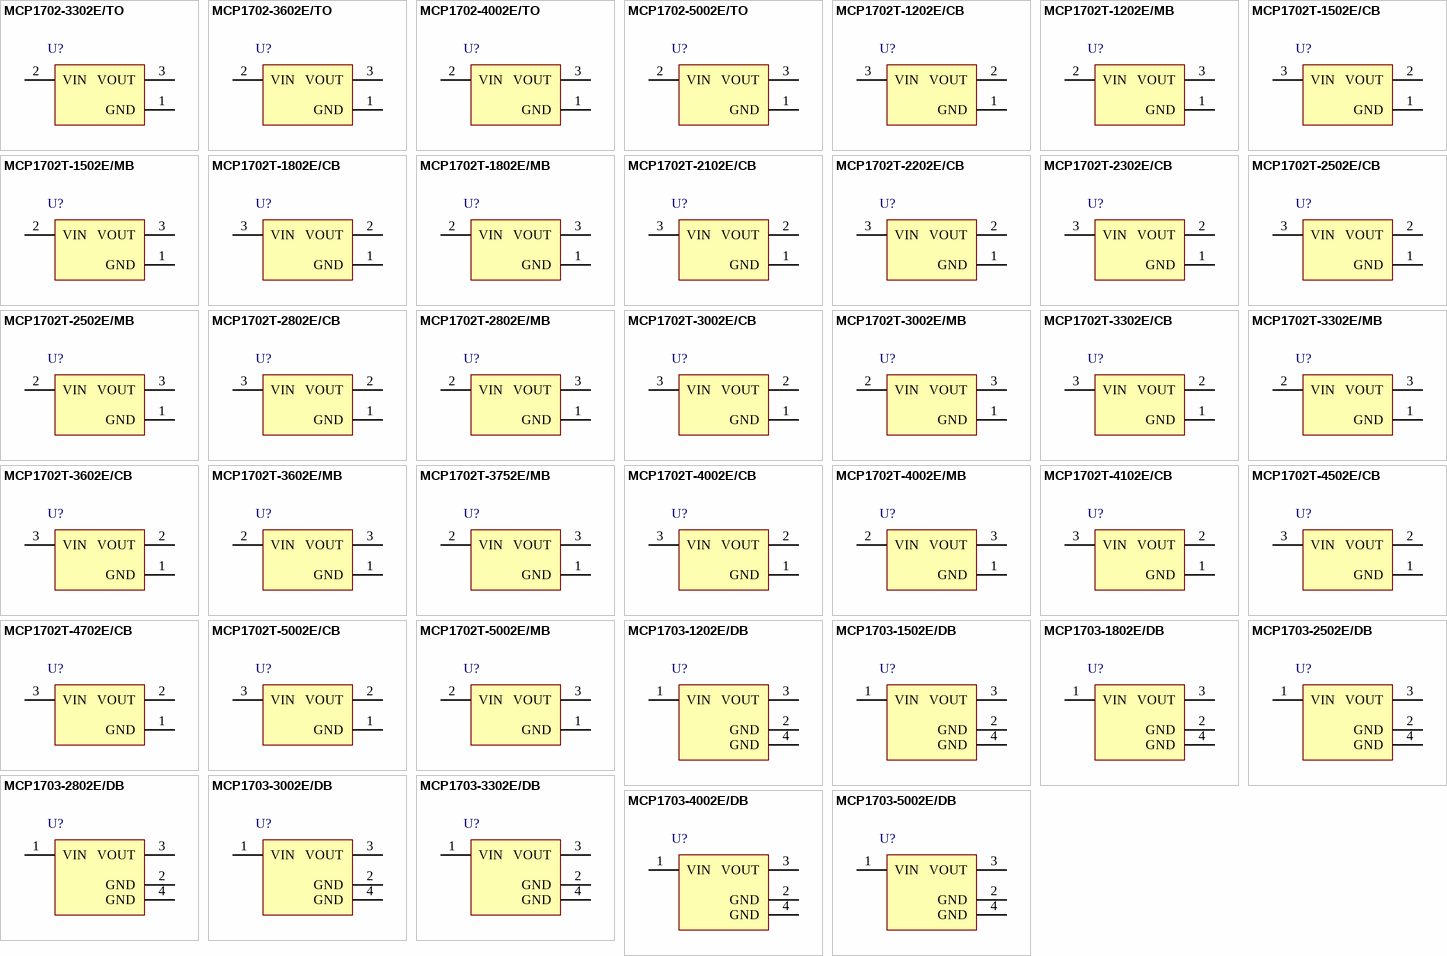
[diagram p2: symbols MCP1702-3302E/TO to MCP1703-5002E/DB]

## MCP1702-3302E/TO
designator U?
250 mA Low Quiescent Current LDO Regulator, 3-Pin TO-92, Extended TemperatureBAG
footprint TO-92-TO3 (TO, Flat Index; 3 In-Line, Axial Leads; Body Dia. 4.8mm; Leads 0.56 x 0.53 mm (max))
pins: 1 GND (power), 2 VIN (power), 3 VOUT (power)

## MCP1702-3602E/TO
designator U?
250 mA Low Quiescent Current LDO Regulator, 3-Pin TO-92, Extended TemperatureBAG
footprint TO-92-TO3 (TO, Flat Index; 3 In-Line, Axial Leads; Body Dia. 4.8mm; Leads 0.56 x 0.53 mm (max))
pins: 1 GND (power), 2 VIN (power), 3 VOUT (power)

## MCP1702-4002E/TO
designator U?
250 mA Low Quiescent Current LDO Regulator, 3-Pin TO-92, Extended TemperatureBAG
footprint TO-92-TO3 (TO, Flat Index; 3 In-Line, Axial Leads; Body Dia. 4.8mm; Leads 0.56 x 0.53 mm (max))
pins: 1 GND (power), 2 VIN (power), 3 VOUT (power)

## MCP1702-5002E/TO
designator U?
250 mA Low Quiescent Current LDO Regulator, 3-Pin TO-92, Extended TemperatureBAG
footprint TO-92-TO3 (TO, Flat Index; 3 In-Line, Axial Leads; Body Dia. 4.8mm; Leads 0.56 x 0.53 mm (max))
pins: 1 GND (power), 2 VIN (power), 3 VOUT (power)

## MCP1702T-1202E/CB
designator U?
250 mA Low Quiescent Current LDO Regulator, 3-Pin SOT-23A, Extended Temperature, Tape and Reel
footprint SOT-23A-CB3_N (SOT346, 3-Leads, Body 2.9x1.5mm, Pitch 0.95mm, Lead Span 2.6mm, IPC Medium Density)
footprint SOT-23A-CB3_L (SOT346, 3-Leads, Body 2.9x1.5mm, Pitch 0.95mm, Lead Span 2.6mm, IPC High Density)
footprint SOT-23A-CB3_M (SOT346, 3-Leads, Body 2.9x1.5mm, Pitch 0.95mm, Lead Span 2.6mm, IPC Low Density)
pins: 1 GND (power), 2 VOUT (power), 3 VIN (power)

## MCP1702T-1202E/MB
designator U?
250 mA Low Quiescent Current LDO Regulator, 3-Pin SOT-89, Extended Temperature, Tape and Reel
footprint SOT-89-MB3_N (SOT89, 3-Leads, Body 4.5x2.4 mm, Pitch 1.5mm, Lead Span 4.1mm, IPC Medium Density)
footprint SOT-89-MB3_L (SOT89, 3-Leads, Body 4.5x2.4 mm, Pitch 1.5mm, Lead Span 4.1mm, IPC High Density)
footprint SOT-89-MB3_M (SOT89, 3-Leads, Body 4.5x2.4 mm, Pitch 1.5mm, Lead Span 4.1mm, IPC Low Density)
pins: 1 GND (power), 2 VIN (power), 3 VOUT (power)

## MCP1702T-1502E/CB
designator U?
250 mA Low Quiescent Current LDO Regulator, 3-Pin SOT-23A, Extended Temperature, Tape and Reel
footprint SOT-23A-CB3_N (SOT346, 3-Leads, Body 2.9x1.5mm, Pitch 0.95mm, Lead Span 2.6mm, IPC Medium Density)
footprint SOT-23A-CB3_L (SOT346, 3-Leads, Body 2.9x1.5mm, Pitch 0.95mm, Lead Span 2.6mm, IPC High Density)
footprint SOT-23A-CB3_M (SOT346, 3-Leads, Body 2.9x1.5mm, Pitch 0.95mm, Lead Span 2.6mm, IPC Low Density)
pins: 1 GND (power), 2 VOUT (power), 3 VIN (power)

## MCP1702T-1502E/MB
designator U?
250 mA Low Quiescent Current LDO Regulator, 3-Pin SOT-89, Extended Temperature, Tape and Reel
footprint SOT-89-MB3_N (SOT89, 3-Leads, Body 4.5x2.4 mm, Pitch 1.5mm, Lead Span 4.1mm, IPC Medium Density)
footprint SOT-89-MB3_L (SOT89, 3-Leads, Body 4.5x2.4 mm, Pitch 1.5mm, Lead Span 4.1mm, IPC High Density)
footprint SOT-89-MB3_M (SOT89, 3-Leads, Body 4.5x2.4 mm, Pitch 1.5mm, Lead Span 4.1mm, IPC Low Density)
pins: 1 GND (power), 2 VIN (power), 3 VOUT (power)

## MCP1702T-1802E/CB
designator U?
250 mA Low Quiescent Current LDO Regulator, 3-Pin SOT-23A, Extended Temperature, Tape and Reel
footprint SOT-23A-CB3_N (SOT346, 3-Leads, Body 2.9x1.5mm, Pitch 0.95mm, Lead Span 2.6mm, IPC Medium Density)
footprint SOT-23A-CB3_L (SOT346, 3-Leads, Body 2.9x1.5mm, Pitch 0.95mm, Lead Span 2.6mm, IPC High Density)
footprint SOT-23A-CB3_M (SOT346, 3-Leads, Body 2.9x1.5mm, Pitch 0.95mm, Lead Span 2.6mm, IPC Low Density)
pins: 1 GND (power), 2 VOUT (power), 3 VIN (power)

## MCP1702T-1802E/MB
designator U?
250 mA Low Quiescent Current LDO Regulator, 3-Pin SOT-89, Extended Temperature, Tape and Reel
footprint SOT-89-MB3_N (SOT89, 3-Leads, Body 4.5x2.4 mm, Pitch 1.5mm, Lead Span 4.1mm, IPC Medium Density)
footprint SOT-89-MB3_L (SOT89, 3-Leads, Body 4.5x2.4 mm, Pitch 1.5mm, Lead Span 4.1mm, IPC High Density)
footprint SOT-89-MB3_M (SOT89, 3-Leads, Body 4.5x2.4 mm, Pitch 1.5mm, Lead Span 4.1mm, IPC Low Density)
pins: 1 GND (power), 2 VIN (power), 3 VOUT (power)

## MCP1702T-2102E/CB
designator U?
250 mA Low Quiescent Current LDO Regulator, 3-Pin SOT-23A, Extended Temperature, Tape and Reel
footprint SOT-23A-CB3_N (SOT346, 3-Leads, Body 2.9x1.5mm, Pitch 0.95mm, Lead Span 2.6mm, IPC Medium Density)
footprint SOT-23A-CB3_L (SOT346, 3-Leads, Body 2.9x1.5mm, Pitch 0.95mm, Lead Span 2.6mm, IPC High Density)
footprint SOT-23A-CB3_M (SOT346, 3-Leads, Body 2.9x1.5mm, Pitch 0.95mm, Lead Span 2.6mm, IPC Low Density)
pins: 1 GND (power), 2 VOUT (power), 3 VIN (power)

## MCP1702T-2202E/CB
designator U?
250 mA Low Quiescent Current LDO Regulator, 3-Pin SOT-23A, Extended Temperature, Tape and Reel
footprint SOT-23A-CB3_N (SOT346, 3-Leads, Body 2.9x1.5mm, Pitch 0.95mm, Lead Span 2.6mm, IPC Medium Density)
footprint SOT-23A-CB3_L (SOT346, 3-Leads, Body 2.9x1.5mm, Pitch 0.95mm, Lead Span 2.6mm, IPC High Density)
footprint SOT-23A-CB3_M (SOT346, 3-Leads, Body 2.9x1.5mm, Pitch 0.95mm, Lead Span 2.6mm, IPC Low Density)
pins: 1 GND (power), 2 VOUT (power), 3 VIN (power)

## MCP1702T-2302E/CB
designator U?
250 mA Low Quiescent Current LDO Regulator, 3-Pin SOT-23A, Extended Temperature, Tape and Reel
footprint SOT-23A-CB3_N (SOT346, 3-Leads, Body 2.9x1.5mm, Pitch 0.95mm, Lead Span 2.6mm, IPC Medium Density)
footprint SOT-23A-CB3_L (SOT346, 3-Leads, Body 2.9x1.5mm, Pitch 0.95mm, Lead Span 2.6mm, IPC High Density)
footprint SOT-23A-CB3_M (SOT346, 3-Leads, Body 2.9x1.5mm, Pitch 0.95mm, Lead Span 2.6mm, IPC Low Density)
pins: 1 GND (power), 2 VOUT (power), 3 VIN (power)

## MCP1702T-2502E/CB
designator U?
250 mA Low Quiescent Current LDO Regulator, 3-Pin SOT-23A, Extended Temperature, Tape and Reel
footprint SOT-23A-CB3_N (SOT346, 3-Leads, Body 2.9x1.5mm, Pitch 0.95mm, Lead Span 2.6mm, IPC Medium Density)
footprint SOT-23A-CB3_L (SOT346, 3-Leads, Body 2.9x1.5mm, Pitch 0.95mm, Lead Span 2.6mm, IPC High Density)
footprint SOT-23A-CB3_M (SOT346, 3-Leads, Body 2.9x1.5mm, Pitch 0.95mm, Lead Span 2.6mm, IPC Low Density)
pins: 1 GND (power), 2 VOUT (power), 3 VIN (power)

## MCP1702T-2502E/MB
designator U?
250 mA Low Quiescent Current LDO Regulator, 3-Pin SOT-89, Extended Temperature, Tape and Reel
footprint SOT-89-MB3_N (SOT89, 3-Leads, Body 4.5x2.4 mm, Pitch 1.5mm, Lead Span 4.1mm, IPC Medium Density)
footprint SOT-89-MB3_L (SOT89, 3-Leads, Body 4.5x2.4 mm, Pitch 1.5mm, Lead Span 4.1mm, IPC High Density)
footprint SOT-89-MB3_M (SOT89, 3-Leads, Body 4.5x2.4 mm, Pitch 1.5mm, Lead Span 4.1mm, IPC Low Density)
pins: 1 GND (power), 2 VIN (power), 3 VOUT (power)

## MCP1702T-2802E/CB
designator U?
250 mA Low Quiescent Current LDO Regulator, 3-Pin SOT-23A, Extended Temperature, Tape and Reel
footprint SOT-23A-CB3_N (SOT346, 3-Leads, Body 2.9x1.5mm, Pitch 0.95mm, Lead Span 2.6mm, IPC Medium Density)
footprint SOT-23A-CB3_L (SOT346, 3-Leads, Body 2.9x1.5mm, Pitch 0.95mm, Lead Span 2.6mm, IPC High Density)
footprint SOT-23A-CB3_M (SOT346, 3-Leads, Body 2.9x1.5mm, Pitch 0.95mm, Lead Span 2.6mm, IPC Low Density)
pins: 1 GND (power), 2 VOUT (power), 3 VIN (power)

## MCP1702T-2802E/MB
designator U?
250 mA Low Quiescent Current LDO Regulator, 3-Pin SOT-89, Extended Temperature, Tape and Reel
footprint SOT-89-MB3_N (SOT89, 3-Leads, Body 4.5x2.4 mm, Pitch 1.5mm, Lead Span 4.1mm, IPC Medium Density)
footprint SOT-89-MB3_L (SOT89, 3-Leads, Body 4.5x2.4 mm, Pitch 1.5mm, Lead Span 4.1mm, IPC High Density)
footprint SOT-89-MB3_M (SOT89, 3-Leads, Body 4.5x2.4 mm, Pitch 1.5mm, Lead Span 4.1mm, IPC Low Density)
pins: 1 GND (power), 2 VIN (power), 3 VOUT (power)

## MCP1702T-3002E/CB
designator U?
250 mA Low Quiescent Current LDO Regulator, 3-Pin SOT-23A, Extended Temperature, Tape and Reel
footprint SOT-23A-CB3_N (SOT346, 3-Leads, Body 2.9x1.5mm, Pitch 0.95mm, Lead Span 2.6mm, IPC Medium Density)
footprint SOT-23A-CB3_L (SOT346, 3-Leads, Body 2.9x1.5mm, Pitch 0.95mm, Lead Span 2.6mm, IPC High Density)
footprint SOT-23A-CB3_M (SOT346, 3-Leads, Body 2.9x1.5mm, Pitch 0.95mm, Lead Span 2.6mm, IPC Low Density)
pins: 1 GND (power), 2 VOUT (power), 3 VIN (power)

## MCP1702T-3002E/MB
designator U?
250 mA Low Quiescent Current LDO Regulator, 3-Pin SOT-89, Extended Temperature, Tape and Reel
footprint SOT-89-MB3_N (SOT89, 3-Leads, Body 4.5x2.4 mm, Pitch 1.5mm, Lead Span 4.1mm, IPC Medium Density)
footprint SOT-89-MB3_L (SOT89, 3-Leads, Body 4.5x2.4 mm, Pitch 1.5mm, Lead Span 4.1mm, IPC High Density)
footprint SOT-89-MB3_M (SOT89, 3-Leads, Body 4.5x2.4 mm, Pitch 1.5mm, Lead Span 4.1mm, IPC Low Density)
pins: 1 GND (power), 2 VIN (power), 3 VOUT (power)

## MCP1702T-3302E/CB
designator U?
250 mA Low Quiescent Current LDO Regulator, 3-Pin SOT-23A, Extended Temperature, Tape and Reel
footprint SOT-23A-CB3_N (SOT346, 3-Leads, Body 2.9x1.5mm, Pitch 0.95mm, Lead Span 2.6mm, IPC Medium Density)
footprint SOT-23A-CB3_L (SOT346, 3-Leads, Body 2.9x1.5mm, Pitch 0.95mm, Lead Span 2.6mm, IPC High Density)
footprint SOT-23A-CB3_M (SOT346, 3-Leads, Body 2.9x1.5mm, Pitch 0.95mm, Lead Span 2.6mm, IPC Low Density)
pins: 1 GND (power), 2 VOUT (power), 3 VIN (power)

## MCP1702T-3302E/MB
designator U?
250 mA Low Quiescent Current LDO Regulator, 3-Pin SOT-89, Extended Temperature, Tape and Reel
footprint SOT-89-MB3_N (SOT89, 3-Leads, Body 4.5x2.4 mm, Pitch 1.5mm, Lead Span 4.1mm, IPC Medium Density)
footprint SOT-89-MB3_L (SOT89, 3-Leads, Body 4.5x2.4 mm, Pitch 1.5mm, Lead Span 4.1mm, IPC High Density)
footprint SOT-89-MB3_M (SOT89, 3-Leads, Body 4.5x2.4 mm, Pitch 1.5mm, Lead Span 4.1mm, IPC Low Density)
pins: 1 GND (power), 2 VIN (power), 3 VOUT (power)

## MCP1702T-3602E/CB
designator U?
250 mA Low Quiescent Current LDO Regulator, 3-Pin SOT-23A, Extended Temperature, Tape and Reel
footprint SOT-23A-CB3_N (SOT346, 3-Leads, Body 2.9x1.5mm, Pitch 0.95mm, Lead Span 2.6mm, IPC Medium Density)
footprint SOT-23A-CB3_L (SOT346, 3-Leads, Body 2.9x1.5mm, Pitch 0.95mm, Lead Span 2.6mm, IPC High Density)
footprint SOT-23A-CB3_M (SOT346, 3-Leads, Body 2.9x1.5mm, Pitch 0.95mm, Lead Span 2.6mm, IPC Low Density)
pins: 1 GND (power), 2 VOUT (power), 3 VIN (power)

## MCP1702T-3602E/MB
designator U?
250 mA Low Quiescent Current LDO Regulator, 3-Pin SOT-89, Extended Temperature, Tape and Reel
footprint SOT-89-MB3_N (SOT89, 3-Leads, Body 4.5x2.4 mm, Pitch 1.5mm, Lead Span 4.1mm, IPC Medium Density)
footprint SOT-89-MB3_L (SOT89, 3-Leads, Body 4.5x2.4 mm, Pitch 1.5mm, Lead Span 4.1mm, IPC High Density)
footprint SOT-89-MB3_M (SOT89, 3-Leads, Body 4.5x2.4 mm, Pitch 1.5mm, Lead Span 4.1mm, IPC Low Density)
pins: 1 GND (power), 2 VIN (power), 3 VOUT (power)

## MCP1702T-3752E/MB
designator U?
250 mA Low Quiescent Current LDO Regulator, 3-Pin SOT-89, Extended Temperature, Tape and Reel
footprint SOT-89-MB3_N (SOT89, 3-Leads, Body 4.5x2.4 mm, Pitch 1.5mm, Lead Span 4.1mm, IPC Medium Density)
footprint SOT-89-MB3_L (SOT89, 3-Leads, Body 4.5x2.4 mm, Pitch 1.5mm, Lead Span 4.1mm, IPC High Density)
footprint SOT-89-MB3_M (SOT89, 3-Leads, Body 4.5x2.4 mm, Pitch 1.5mm, Lead Span 4.1mm, IPC Low Density)
pins: 1 GND (power), 2 VIN (power), 3 VOUT (power)

## MCP1702T-4002E/CB
designator U?
250 mA Low Quiescent Current LDO Regulator, 3-Pin SOT-23A, Extended Temperature, Tape and Reel
footprint SOT-23A-CB3_N (SOT346, 3-Leads, Body 2.9x1.5mm, Pitch 0.95mm, Lead Span 2.6mm, IPC Medium Density)
footprint SOT-23A-CB3_L (SOT346, 3-Leads, Body 2.9x1.5mm, Pitch 0.95mm, Lead Span 2.6mm, IPC High Density)
footprint SOT-23A-CB3_M (SOT346, 3-Leads, Body 2.9x1.5mm, Pitch 0.95mm, Lead Span 2.6mm, IPC Low Density)
pins: 1 GND (power), 2 VOUT (power), 3 VIN (power)

## MCP1702T-4002E/MB
designator U?
250 mA Low Quiescent Current LDO Regulator, 3-Pin SOT-89, Extended Temperature, Tape and Reel
footprint SOT-89-MB3_N (SOT89, 3-Leads, Body 4.5x2.4 mm, Pitch 1.5mm, Lead Span 4.1mm, IPC Medium Density)
footprint SOT-89-MB3_L (SOT89, 3-Leads, Body 4.5x2.4 mm, Pitch 1.5mm, Lead Span 4.1mm, IPC High Density)
footprint SOT-89-MB3_M (SOT89, 3-Leads, Body 4.5x2.4 mm, Pitch 1.5mm, Lead Span 4.1mm, IPC Low Density)
pins: 1 GND (power), 2 VIN (power), 3 VOUT (power)

## MCP1702T-4102E/CB
designator U?
250 mA Low Quiescent Current LDO Regulator, 3-Pin SOT-23A, Extended Temperature, Tape and Reel
footprint SOT-23A-CB3_N (SOT346, 3-Leads, Body 2.9x1.5mm, Pitch 0.95mm, Lead Span 2.6mm, IPC Medium Density)
footprint SOT-23A-CB3_L (SOT346, 3-Leads, Body 2.9x1.5mm, Pitch 0.95mm, Lead Span 2.6mm, IPC High Density)
footprint SOT-23A-CB3_M (SOT346, 3-Leads, Body 2.9x1.5mm, Pitch 0.95mm, Lead Span 2.6mm, IPC Low Density)
pins: 1 GND (power), 2 VOUT (power), 3 VIN (power)

## MCP1702T-4502E/CB
designator U?
250 mA Low Quiescent Current LDO Regulator, 3-Pin SOT-23A, Extended Temperature, Tape and Reel
footprint SOT-23A-CB3_N (SOT346, 3-Leads, Body 2.9x1.5mm, Pitch 0.95mm, Lead Span 2.6mm, IPC Medium Density)
footprint SOT-23A-CB3_L (SOT346, 3-Leads, Body 2.9x1.5mm, Pitch 0.95mm, Lead Span 2.6mm, IPC High Density)
footprint SOT-23A-CB3_M (SOT346, 3-Leads, Body 2.9x1.5mm, Pitch 0.95mm, Lead Span 2.6mm, IPC Low Density)
pins: 1 GND (power), 2 VOUT (power), 3 VIN (power)

## MCP1702T-4702E/CB
designator U?
250 mA Low Quiescent Current LDO Regulator, 3-Pin SOT-23A, Extended Temperature, Tape and Reel
footprint SOT-23A-CB3_N (SOT346, 3-Leads, Body 2.9x1.5mm, Pitch 0.95mm, Lead Span 2.6mm, IPC Medium Density)
footprint SOT-23A-CB3_L (SOT346, 3-Leads, Body 2.9x1.5mm, Pitch 0.95mm, Lead Span 2.6mm, IPC High Density)
footprint SOT-23A-CB3_M (SOT346, 3-Leads, Body 2.9x1.5mm, Pitch 0.95mm, Lead Span 2.6mm, IPC Low Density)
pins: 1 GND (power), 2 VOUT (power), 3 VIN (power)

## MCP1702T-5002E/CB
designator U?
250 mA Low Quiescent Current LDO Regulator, 3-Pin SOT-23A, Extended Temperature, Tape and Reel
footprint SOT-23A-CB3_N (SOT346, 3-Leads, Body 2.9x1.5mm, Pitch 0.95mm, Lead Span 2.6mm, IPC Medium Density)
footprint SOT-23A-CB3_L (SOT346, 3-Leads, Body 2.9x1.5mm, Pitch 0.95mm, Lead Span 2.6mm, IPC High Density)
footprint SOT-23A-CB3_M (SOT346, 3-Leads, Body 2.9x1.5mm, Pitch 0.95mm, Lead Span 2.6mm, IPC Low Density)
pins: 1 GND (power), 2 VOUT (power), 3 VIN (power)

## MCP1702T-5002E/MB
designator U?
250 mA Low Quiescent Current LDO Regulator, 3-Pin SOT-89, Extended Temperature, Tape and Reel
footprint SOT-89-MB3_N (SOT89, 3-Leads, Body 4.5x2.4 mm, Pitch 1.5mm, Lead Span 4.1mm, IPC Medium Density)
footprint SOT-89-MB3_L (SOT89, 3-Leads, Body 4.5x2.4 mm, Pitch 1.5mm, Lead Span 4.1mm, IPC High Density)
footprint SOT-89-MB3_M (SOT89, 3-Leads, Body 4.5x2.4 mm, Pitch 1.5mm, Lead Span 4.1mm, IPC Low Density)
pins: 1 GND (power), 2 VIN (power), 3 VOUT (power)

## MCP1703-1202E/DB
designator U?
250 mA, 16V, Low Quiescent Current LDO Regulator, 3-Pin SOT-223, Extended Temperature
footprint SOT-223-DB3_N (SOT223, 4-Leads, Body 6.5x3.5mm, Pitch 2.3mm, Lead Span 7mm, IPC Medium Density)
footprint SOT-223-DB3_L (SOT223, 4-Leads, Body 6.5x3.5mm, Pitch 2.3mm, Lead Span 7mm, IPC High Density)
footprint SOT-223-DB3_M (SOT223, 4-Leads, Body 6.5x3.5mm, Pitch 2.3mm, Lead Span 7mm, IPC Low Density)
pins: 1 VIN (power), 2 GND (power), 3 VOUT (power), 4 GND (power)

## MCP1703-1502E/DB
designator U?
250 mA, 16V, Low Quiescent Current LDO Regulator, 3-Pin SOT-223, Extended Temperature
footprint SOT-223-DB3_N (SOT223, 4-Leads, Body 6.5x3.5mm, Pitch 2.3mm, Lead Span 7mm, IPC Medium Density)
footprint SOT-223-DB3_L (SOT223, 4-Leads, Body 6.5x3.5mm, Pitch 2.3mm, Lead Span 7mm, IPC High Density)
footprint SOT-223-DB3_M (SOT223, 4-Leads, Body 6.5x3.5mm, Pitch 2.3mm, Lead Span 7mm, IPC Low Density)
pins: 1 VIN (power), 2 GND (power), 3 VOUT (power), 4 GND (power)

## MCP1703-1802E/DB
designator U?
250 mA, 16V, Low Quiescent Current LDO Regulator, 3-Pin SOT-223, Extended Temperature
footprint SOT-223-DB3_N (SOT223, 4-Leads, Body 6.5x3.5mm, Pitch 2.3mm, Lead Span 7mm, IPC Medium Density)
footprint SOT-223-DB3_L (SOT223, 4-Leads, Body 6.5x3.5mm, Pitch 2.3mm, Lead Span 7mm, IPC High Density)
footprint SOT-223-DB3_M (SOT223, 4-Leads, Body 6.5x3.5mm, Pitch 2.3mm, Lead Span 7mm, IPC Low Density)
pins: 1 VIN (power), 2 GND (power), 3 VOUT (power), 4 GND (power)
